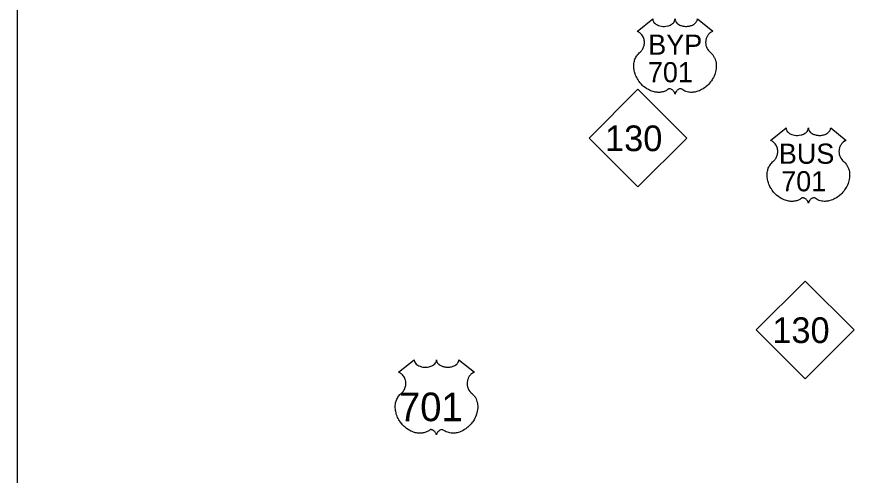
# Model space of a CAD drawing. Extents: x 5197761 to 5514561, y 1890130 to 2080942.
# Drawn here: x 5298905 to 5322096, y 1997380 to 2009899 of the extents above; entities that cross this region are included whole.
import ezdxf

# ---------------------------------------------------------------- set-up
doc = ezdxf.new("R2010")
doc.units = 0
for name, color, linetype in [('Exist Road Primary NC Shield CELL', 7, 'Continuous'), ('Exist Road Primary NC Shield Number Label', 7, 'Continuous'), ('Exist Road Primary US Shield CELL', 7, 'Continuous'), ('Exist Road Primary US Shield Number Label', 7, 'Continuous'), ('Map Preparation Inset Cut Line', 7, 'Continuous')]:
    doc.layers.add(name, color=color, linetype=linetype)

msp = doc.modelspace()

# ---------------------------------------------------------------- linework, layer by layer
at = {"layer": 'Exist Road Primary NC Shield CELL'}
for points in [[(5314494, 2006598), (5315826, 2007930), (5317158, 2006598), (5315826, 2005266)], [(5319051, 2001366), (5320383, 2002698), (5321715, 2001366), (5320383, 2000034)]]:
    msp.add_lwpolyline(points, close=True, dxfattribs=at)
at = {"layer": 'Exist Road Primary US Shield CELL'}
for points in [[(5316229, 2009846), (5316230, 2009829), (5316234, 2009808), (5316238, 2009797), (5316247, 2009777), (5316263, 2009752), (5316286, 2009728), (5316311, 2009707), (5316328, 2009696), (5316357, 2009681), (5316390, 2009667), (5316427, 2009656), (5316464, 2009649), (5316505, 2009644), (5316546, 2009644), (5316589, 2009647), (5316637, 2009656), (5316660, 2009662), (5316685, 2009671), (5316708, 2009680), (5316733, 2009694), (5316753, 2009707), (5316769, 2009718), (5316792, 2009740), (5316810, 2009762), (5316818, 2009775), (5316824, 2009787), (5316833, 2009812), (5316835, 2009824), (5316837, 2009847), (5316839, 2009828), (5316841, 2009815), (5316844, 2009803), (5316849, 2009790), (5316858, 2009772), (5316868, 2009757), (5316887, 2009735), (5316899, 2009724), (5316910, 2009715), (5316939, 2009695), (5316972, 2009678), (5316989, 2009671), (5317006, 2009665), (5317028, 2009658), (5317050, 2009653), (5317072, 2009649), (5317095, 2009646), (5317118, 2009644), (5317136, 2009644), (5317160, 2009644), (5317181, 2009645), (5317203, 2009648), (5317227, 2009652), (5317246, 2009656), (5317272, 2009663), (5317295, 2009671), (5317315, 2009680), (5317342, 2009694), (5317363, 2009707), (5317379, 2009720), (5317397, 2009737), (5317415, 2009757), (5317425, 2009772), (5317432, 2009787), (5317439, 2009803), (5317443, 2009820), (5317445, 2009835), (5317446, 2009848), (5317871, 2009509), (5317861, 2009505), (5317838, 2009494), (5317819, 2009483), (5317790, 2009463), (5317777, 2009451), (5317765, 2009439), (5317753, 2009427), (5317743, 2009415), (5317731, 2009398), (5317720, 2009381), (5317709, 2009362), (5317701, 2009346), (5317688, 2009312), (5317682, 2009290), (5317678, 2009272), (5317673, 2009234), (5317672, 2009216), (5317672, 2009198), (5317673, 2009179), (5317674, 2009161), (5317678, 2009142), (5317681, 2009125), (5317686, 2009105), (5317693, 2009081), (5317703, 2009059), (5317722, 2009022), (5317747, 2008984), (5317765, 2008963), (5317782, 2008945), (5317809, 2008923), (5317823, 2008910), (5317839, 2008894), (5317866, 2008863), (5317877, 2008848), (5317888, 2008832), (5317898, 2008815), (5317908, 2008797), (5317916, 2008781), (5317931, 2008745), (5317942, 2008709), (5317947, 2008691), (5317954, 2008649), (5317957, 2008629), (5317961, 2008588), (5317961, 2008539), (5317957, 2008492), (5317948, 2008437), (5317941, 2008405), (5317930, 2008367), (5317919, 2008334), (5317900, 2008285), (5317882, 2008250), (5317860, 2008209), (5317845, 2008184), (5317827, 2008158), (5317805, 2008127), (5317778, 2008094), (5317747, 2008060), (5317722, 2008034), (5317689, 2008005), (5317668, 2007988), (5317640, 2007967), (5317601, 2007941), (5317562, 2007918), (5317529, 2007901), (5317500, 2007889), (5317462, 2007874), (5317400, 2007857), (5317377, 2007852), (5317350, 2007848), (5317324, 2007846), (5317300, 2007844), (5317267, 2007844), (5317234, 2007847), (5317203, 2007851), (5317170, 2007858), (5317136, 2007868), (5317105, 2007880), (5317074, 2007896), (5317022, 2007929), (5317007, 2007937), (5316998, 2007939), (5316978, 2007940), (5316959, 2007936), (5316939, 2007928), (5316927, 2007922), (5316912, 2007912), (5316899, 2007902), (5316885, 2007888), (5316875, 2007877), (5316867, 2007868), (5316852, 2007844), (5316847, 2007833), (5316842, 2007819), (5316837, 2007798), (5316830, 2007824), (5316822, 2007842), (5316813, 2007857), (5316804, 2007870), (5316789, 2007888), (5316776, 2007900), (5316760, 2007913), (5316743, 2007924), (5316729, 2007931), (5316716, 2007936), (5316701, 2007939), (5316688, 2007940), (5316678, 2007940), (5316664, 2007937), (5316645, 2007923), (5316627, 2007910), (5316607, 2007898), (5316583, 2007886), (5316566, 2007877), (5316545, 2007869), (5316521, 2007861), (5316495, 2007855), (5316468, 2007849), (5316445, 2007846), (5316419, 2007843), (5316396, 2007843), (5316372, 2007843), (5316350, 2007845), (5316324, 2007847), (5316292, 2007852), (5316266, 2007858), (5316237, 2007865), (5316209, 2007874), (5316178, 2007886), (5316139, 2007903), (5316112, 2007917), (5316070, 2007941), (5316020, 2007975), (5315982, 2008006), (5315955, 2008031), (5315915, 2008072), (5315891, 2008099), (5315854, 2008147), (5315830, 2008182), (5315814, 2008208), (5315792, 2008249), (5315779, 2008275), (5315763, 2008312), (5315750, 2008347), (5315740, 2008379), (5315734, 2008400), (5315726, 2008437), (5315721, 2008463), (5315717, 2008498), (5315714, 2008535), (5315713, 2008570), (5315714, 2008598), (5315718, 2008632), (5315723, 2008667), (5315730, 2008698), (5315736, 2008720), (5315745, 2008746), (5315757, 2008776), (5315771, 2008804), (5315785, 2008827), (5315801, 2008852), (5315818, 2008873), (5315840, 2008897), (5315862, 2008919), (5315883, 2008936), (5315908, 2008960), (5315920, 2008974), (5315936, 2008995), (5315948, 2009013), (5315958, 2009030), (5315971, 2009055), (5315979, 2009074), (5315989, 2009102), (5315993, 2009122), (5315998, 2009148), (5316002, 2009173), (5316003, 2009203), (5316002, 2009228), (5315999, 2009258), (5315993, 2009286), (5315987, 2009310), (5315976, 2009338), (5315967, 2009359), (5315950, 2009387), (5315932, 2009413), (5315913, 2009434), (5315895, 2009453), (5315877, 2009467), (5315859, 2009479), (5315838, 2009492), (5315817, 2009502), (5315804, 2009508)], [(5319862, 2006872), (5319863, 2006855), (5319867, 2006834), (5319871, 2006823), (5319880, 2006803), (5319896, 2006778), (5319919, 2006754), (5319944, 2006733), (5319961, 2006722), (5319990, 2006707), (5320023, 2006693), (5320060, 2006682), (5320097, 2006675), (5320138, 2006670), (5320179, 2006670), (5320222, 2006673), (5320271, 2006682), (5320293, 2006688), (5320318, 2006697), (5320341, 2006706), (5320366, 2006720), (5320387, 2006733), (5320403, 2006744), (5320425, 2006766), (5320443, 2006788), (5320451, 2006801), (5320457, 2006813), (5320466, 2006838), (5320469, 2006850), (5320470, 2006873), (5320472, 2006854), (5320474, 2006841), (5320477, 2006829), (5320482, 2006816), (5320491, 2006798), (5320501, 2006783), (5320520, 2006761), (5320532, 2006750), (5320543, 2006741), (5320572, 2006721), (5320605, 2006704), (5320622, 2006697), (5320639, 2006691), (5320661, 2006684), (5320683, 2006679), (5320705, 2006675), (5320728, 2006672), (5320751, 2006670), (5320770, 2006670), (5320793, 2006670), (5320814, 2006671), (5320836, 2006674), (5320860, 2006678), (5320879, 2006682), (5320905, 2006689), (5320928, 2006697), (5320948, 2006706), (5320975, 2006720), (5320996, 2006733), (5321012, 2006745), (5321030, 2006763), (5321048, 2006783), (5321058, 2006798), (5321065, 2006813), (5321072, 2006829), (5321076, 2006846), (5321078, 2006861), (5321079, 2006874), (5321504, 2006535), (5321494, 2006531), (5321471, 2006520), (5321452, 2006509), (5321423, 2006489), (5321411, 2006477), (5321398, 2006465), (5321386, 2006453), (5321376, 2006441), (5321364, 2006424), (5321353, 2006407), (5321342, 2006388), (5321334, 2006372), (5321321, 2006338), (5321315, 2006316), (5321311, 2006298), (5321306, 2006260), (5321305, 2006242), (5321305, 2006224), (5321306, 2006205), (5321307, 2006187), (5321311, 2006168), (5321314, 2006151), (5321319, 2006131), (5321326, 2006107), (5321336, 2006085), (5321355, 2006048), (5321380, 2006010), (5321398, 2005989), (5321416, 2005971), (5321442, 2005949), (5321456, 2005936), (5321472, 2005920), (5321499, 2005889), (5321510, 2005874), (5321521, 2005858), (5321531, 2005841), (5321541, 2005823), (5321549, 2005807), (5321564, 2005771), (5321575, 2005735), (5321580, 2005717), (5321588, 2005675), (5321591, 2005655), (5321594, 2005614), (5321594, 2005565), (5321590, 2005518), (5321581, 2005463), (5321574, 2005431), (5321563, 2005393), (5321552, 2005360), (5321533, 2005311), (5321515, 2005276), (5321493, 2005235), (5321478, 2005210), (5321460, 2005184), (5321438, 2005153), (5321412, 2005120), (5321380, 2005086), (5321355, 2005060), (5321322, 2005031), (5321302, 2005014), (5321273, 2004993), (5321234, 2004967), (5321195, 2004944), (5321162, 2004927), (5321133, 2004915), (5321095, 2004900), (5321033, 2004883), (5321010, 2004878), (5320983, 2004874), (5320957, 2004872), (5320933, 2004870), (5320900, 2004870), (5320867, 2004873), (5320836, 2004877), (5320803, 2004884), (5320769, 2004894), (5320739, 2004906), (5320707, 2004922), (5320655, 2004955), (5320640, 2004963), (5320631, 2004965), (5320611, 2004966), (5320592, 2004962), (5320572, 2004954), (5320560, 2004948), (5320545, 2004938), (5320533, 2004928), (5320518, 2004914), (5320508, 2004903), (5320500, 2004894), (5320485, 2004870), (5320480, 2004859), (5320475, 2004845), (5320470, 2004824), (5320463, 2004850), (5320455, 2004868), (5320446, 2004883), (5320437, 2004896), (5320422, 2004914), (5320409, 2004926), (5320393, 2004939), (5320376, 2004950), (5320362, 2004957), (5320349, 2004961), (5320334, 2004965), (5320322, 2004966), (5320311, 2004966), (5320297, 2004963), (5320278, 2004949), (5320260, 2004936), (5320240, 2004924), (5320216, 2004911), (5320199, 2004903), (5320178, 2004895), (5320154, 2004887), (5320128, 2004881), (5320101, 2004875), (5320078, 2004872), (5320052, 2004869), (5320029, 2004869), (5320006, 2004869), (5319983, 2004871), (5319957, 2004873), (5319925, 2004878), (5319899, 2004884), (5319871, 2004891), (5319842, 2004900), (5319811, 2004912), (5319772, 2004929), (5319745, 2004943), (5319703, 2004967), (5319653, 2005001), (5319616, 2005032), (5319588, 2005057), (5319548, 2005098), (5319524, 2005125), (5319487, 2005173), (5319463, 2005208), (5319447, 2005234), (5319425, 2005275), (5319412, 2005301), (5319396, 2005338), (5319384, 2005373), (5319373, 2005405), (5319367, 2005426), (5319359, 2005463), (5319354, 2005488), (5319350, 2005524), (5319347, 2005561), (5319347, 2005596), (5319347, 2005624), (5319351, 2005658), (5319356, 2005693), (5319363, 2005724), (5319369, 2005745), (5319378, 2005772), (5319390, 2005801), (5319404, 2005830), (5319418, 2005853), (5319435, 2005878), (5319451, 2005899), (5319473, 2005923), (5319495, 2005945), (5319516, 2005961), (5319541, 2005986), (5319554, 2006000), (5319569, 2006021), (5319581, 2006039), (5319591, 2006056), (5319604, 2006081), (5319612, 2006100), (5319622, 2006128), (5319627, 2006148), (5319632, 2006174), (5319635, 2006199), (5319636, 2006229), (5319635, 2006254), (5319632, 2006284), (5319627, 2006312), (5319620, 2006336), (5319609, 2006364), (5319600, 2006385), (5319583, 2006413), (5319565, 2006439), (5319547, 2006460), (5319528, 2006479), (5319510, 2006493), (5319492, 2006505), (5319471, 2006518), (5319450, 2006528), (5319437, 2006534)], [(5309728, 2000550), (5309729, 2000532), (5309733, 2000512), (5309736, 2000501), (5309746, 2000480), (5309762, 2000456), (5309785, 2000432), (5309810, 2000411), (5309827, 2000400), (5309856, 2000384), (5309889, 2000371), (5309926, 2000360), (5309963, 2000352), (5310004, 2000348), (5310044, 2000347), (5310088, 2000350), (5310136, 2000360), (5310159, 2000366), (5310183, 2000374), (5310207, 2000384), (5310232, 2000397), (5310252, 2000410), (5310268, 2000422), (5310291, 2000443), (5310309, 2000466), (5310316, 2000478), (5310323, 2000490), (5310332, 2000516), (5310334, 2000527), (5310336, 2000551), (5310337, 2000531), (5310340, 2000519), (5310343, 2000507), (5310348, 2000494), (5310357, 2000476), (5310367, 2000461), (5310386, 2000438), (5310398, 2000427), (5310408, 2000419), (5310437, 2000399), (5310471, 2000382), (5310488, 2000374), (5310505, 2000368), (5310526, 2000362), (5310549, 2000357), (5310571, 2000353), (5310593, 2000349), (5310616, 2000348), (5310635, 2000347), (5310658, 2000347), (5310680, 2000349), (5310702, 2000351), (5310726, 2000355), (5310745, 2000360), (5310771, 2000366), (5310794, 2000375), (5310814, 2000383), (5310840, 2000397), (5310862, 2000411), (5310877, 2000423), (5310896, 2000440), (5310913, 2000461), (5310924, 2000475), (5310931, 2000491), (5310938, 2000507), (5310942, 2000524), (5310944, 2000539), (5310944, 2000551), (5311369, 2000213), (5311359, 2000209), (5311336, 2000198), (5311318, 2000187), (5311289, 2000166), (5311276, 2000155), (5311264, 2000143), (5311252, 2000130), (5311242, 2000119), (5311230, 2000102), (5311219, 2000084), (5311208, 2000066), (5311200, 2000049), (5311187, 2000015), (5311181, 1999994), (5311177, 1999975), (5311172, 1999937), (5311170, 1999919), (5311170, 1999901), (5311171, 1999882), (5311173, 1999864), (5311176, 1999846), (5311179, 1999829), (5311185, 1999809), (5311192, 1999785), (5311201, 1999762), (5311221, 1999725), (5311246, 1999688), (5311264, 1999666), (5311281, 1999648), (5311307, 1999626), (5311322, 1999614), (5311338, 1999597), (5311365, 1999566), (5311375, 1999552), (5311386, 1999536), (5311396, 1999519), (5311406, 1999501), (5311414, 1999485), (5311429, 1999448), (5311440, 1999413), (5311445, 1999394), (5311453, 1999353), (5311456, 1999332), (5311460, 1999291), (5311460, 1999242), (5311456, 1999195), (5311447, 1999141), (5311440, 1999108), (5311429, 1999070), (5311418, 1999037), (5311398, 1998989), (5311381, 1998954), (5311359, 1998913), (5311344, 1998888), (5311326, 1998861), (5311303, 1998830), (5311277, 1998798), (5311246, 1998763), (5311220, 1998738), (5311187, 1998708), (5311167, 1998692), (5311139, 1998670), (5311099, 1998644), (5311061, 1998622), (5311028, 1998605), (5310999, 1998592), (5310961, 1998578), (5310898, 1998561), (5310876, 1998556), (5310848, 1998552), (5310823, 1998549), (5310798, 1998548), (5310765, 1998548), (5310732, 1998550), (5310701, 1998555), (5310669, 1998562), (5310635, 1998572), (5310604, 1998584), (5310573, 1998599), (5310521, 1998632), (5310505, 1998640), (5310497, 1998643), (5310476, 1998644), (5310457, 1998640), (5310438, 1998632), (5310426, 1998626), (5310410, 1998615), (5310398, 1998606), (5310384, 1998592), (5310374, 1998580), (5310366, 1998571), (5310351, 1998548), (5310346, 1998537), (5310340, 1998523), (5310336, 1998501), (5310329, 1998528), (5310321, 1998546), (5310312, 1998561), (5310303, 1998574), (5310288, 1998591), (5310274, 1998604), (5310258, 1998617), (5310241, 1998627), (5310228, 1998634), (5310215, 1998639), (5310200, 1998643), (5310187, 1998644), (5310177, 1998644), (5310163, 1998640), (5310144, 1998627), (5310125, 1998614), (5310106, 1998602), (5310082, 1998589), (5310065, 1998581), (5310044, 1998573), (5310020, 1998565), (5309994, 1998558), (5309967, 1998553), (5309943, 1998549), (5309918, 1998547), (5309895, 1998546), (5309871, 1998546), (5309849, 1998548), (5309823, 1998550), (5309791, 1998555), (5309764, 1998561), (5309736, 1998569), (5309707, 1998578), (5309676, 1998590), (5309638, 1998606), (5309611, 1998620), (5309568, 1998645), (5309519, 1998679), (5309481, 1998709), (5309454, 1998734), (5309413, 1998775), (5309390, 1998802), (5309352, 1998851), (5309328, 1998885), (5309313, 1998911), (5309290, 1998952), (5309278, 1998978), (5309262, 1999016), (5309249, 1999050), (5309239, 1999083), (5309233, 1999104), (5309225, 1999140), (5309220, 1999166), (5309215, 1999201), (5309213, 1999239), (5309212, 1999273), (5309213, 1999302), (5309216, 1999335), (5309222, 1999371), (5309229, 1999401), (5309235, 1999423), (5309244, 1999450), (5309256, 1999479), (5309270, 1999507), (5309283, 1999531), (5309300, 1999556), (5309317, 1999577), (5309339, 1999601), (5309361, 1999622), (5309382, 1999639), (5309406, 1999663), (5309419, 1999678), (5309435, 1999698), (5309447, 1999717), (5309457, 1999734), (5309470, 1999759), (5309478, 1999777), (5309487, 1999806), (5309492, 1999826), (5309497, 1999852), (5309500, 1999876), (5309502, 1999907), (5309501, 1999932), (5309498, 1999961), (5309492, 1999989), (5309486, 2000014), (5309475, 2000042), (5309465, 2000063), (5309449, 2000090), (5309431, 2000116), (5309412, 2000137), (5309393, 2000156), (5309375, 2000170), (5309358, 2000183), (5309337, 2000196), (5309316, 2000206), (5309303, 2000211)]]:
    msp.add_lwpolyline(points, close=True, dxfattribs=at)
at = {"layer": 'Map Preparation Inset Cut Line'}
msp.add_lwpolyline([(5337121, 2027499), (5337121, 2030497), (5298905, 2030497), (5298905, 1990962), (5337121, 1990962), (5337121, 1992535)], dxfattribs=at)

# ---------------------------------------------------------------- texts
at = {"layer": 'Exist Road Primary NC Shield Number Label'}
for p in [(5314930, 2006240), (5319488, 2001007)]:
    msp.add_text('130', height=700, dxfattribs=at).set_placement(p)
at = {"layer": 'Exist Road Primary US Shield Number Label'}
for s, height, p in [('BYP', 550, (5316107, 2008870)), ('701', 550, (5316097, 2008118)), ('BUS', 550, (5319666, 2005896)), ('701', 550, (5319730, 2005144)), ('701', 780, (5309312, 1998875))]:
    msp.add_text(s, height=height, dxfattribs=at).set_placement(p)

doc.saveas('drawing.dxf')
